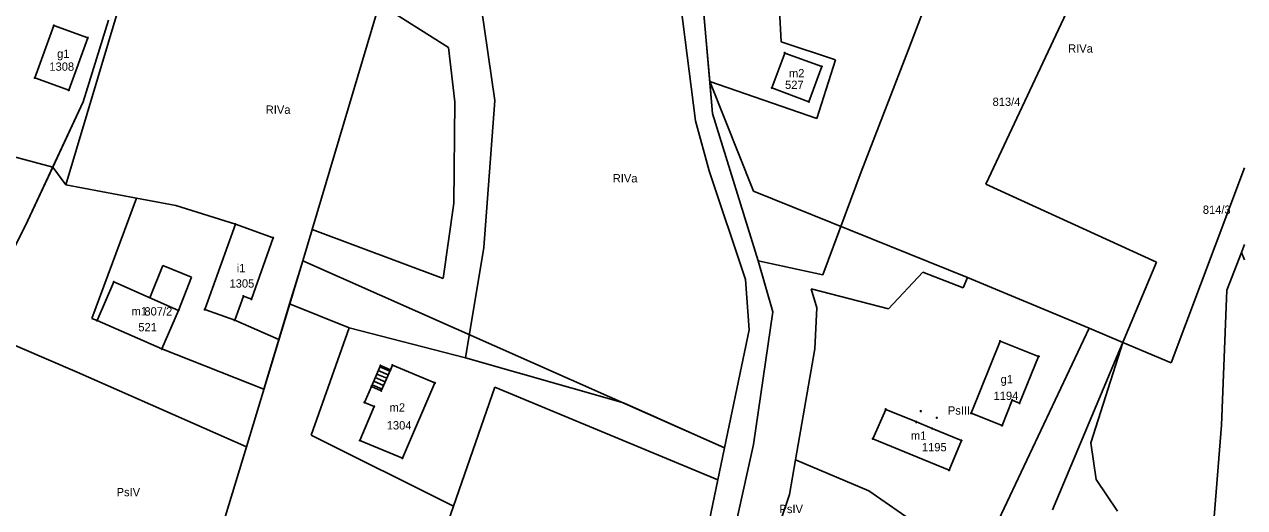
# Model space of a CAD drawing. Extents: x 7498273 to 7499989, y 5499795 to 5500810.
# Drawn here: x 7499768.9 to 7499988.9, y 5500368.1 to 5500455.2 of the extents above; entities that cross this region are included whole.
import ezdxf

# ---------------------------------------------------------------- set-up
doc = ezdxf.new("R2010")
doc.units = 0
for name, color, linetype in [('209-oznaczenie konturu klasyfikacyjnego', 7, 'Continuous'), ('211-numer działki ewidencyjnej', 7, 'Continuous'), ('217-kontur klasyfikacyjny', 7, 'Continuous'), ('218-kontur użytku gruntowego', 7, 'Continuous'), ('219-działka ewidencyjna', 7, 'Continuous'), ('312-budynek ewidencyjny', 7, 'Continuous'), ('312-oznaczenie budynku ewidencyjnego', 7, 'Continuous'), ('312-oznaczenie budynku ewidencyjnego-Atr117', 7, 'Continuous'), ('352-schody', 7, 'Continuous'), ('Punkt budynku', 7, 'Continuous')]:
    doc.layers.add(name, color=color, linetype=linetype)

# ---------------------------------------------------------------- blocks, each defined once
blk = doc.blocks.new('PUNKTBUD')
blk.add_circle((0, 0), 0.09)

msp = doc.modelspace()

# ---------------------------------------------------------------- linework, layer by layer
at = {"layer": '217-kontur klasyfikacyjny'}
for points in [[(7499791.73, 5500477.78), (7499776.34, 5500426.27)], [(7499845.38, 5500451.07), (7499807.05, 5500475.27)], [(7499889.91, 5500437.86), (7499886.1, 5500467.61)], [(7499904.64, 5500464.65), (7499905.33, 5500452.05)], [(7499851.23, 5500458.52), (7499853.72, 5500441.52)], [(7499784.04, 5500455.98), (7499779.48, 5500441.28)], [(7499905.33, 5500452.05), (7499915.14, 5500448.84)], [(7499846.48, 5500441.28), (7499845.38, 5500451.07)], [(7499915.14, 5500448.84), (7499911.74, 5500438.24)], [(7499900.36, 5500425.15), (7499892.44, 5500444.94)], [(7499892.44, 5500444.94), (7499892.94, 5500439.15)], [(7499911.74, 5500438.24), (7499892.44, 5500444.94)], [(7499779.48, 5500441.28), (7499774, 5500429.5)], [(7499846.31, 5500422.98), (7499846.48, 5500441.28)], [(7499853.72, 5500441.52), (7499851.71, 5500415.02)], [(7499892.94, 5500439.15), (7499901.18, 5500412.6)], [(7499892.35, 5500428.8), (7499889.91, 5500437.86)], [(7499774, 5500429.5), (7499764.8, 5500431.96)], [(7499769.06, 5500418.86), (7499774, 5500429.5)], [(7499774, 5500429.5), (7499776.34, 5500426.27)], [(7499975.64, 5500394.23), (7499988.876, 5500429.339)], [(7499898.91, 5500409.21), (7499892.35, 5500428.8)], [(7499776.34, 5500426.27), (7499789.08, 5500423.88)], [(7499938.93, 5500409.6), (7499900.36, 5500425.15)], [(7499781.08, 5500402.21), (7499789.08, 5500423.88)], [(7499789.08, 5500423.88), (7499796.18, 5500422.56)], [(7499796.18, 5500422.56), (7499806.94, 5500419.18)], [(7499844.37, 5500409.4), (7499846.31, 5500422.98)], [(7499762.17, 5500405.33), (7499769.06, 5500418.86)], [(7499806.94, 5500419.18), (7499813.76, 5500416.74)], [(7499819.07, 5500412.57), (7499820.76, 5500418.24)], [(7499820.76, 5500418.24), (7499844.37, 5500409.4)], [(7499813.76, 5500416.74), (7499809.81, 5500405.71)], [(7499851.71, 5500415.02), (7499848.4, 5500395.08)], [(7499985.69, 5500407.28), (7499988.34, 5500414.09)], [(7499988.34, 5500414.09), (7499988.876, 5500412.747)], [(7499816.72, 5500404.82), (7499819.07, 5500412.57)], [(7499901.18, 5500412.6), (7499903.83, 5500403.38)], [(7499924.65, 5500403.92), (7499930.86, 5500410.57)], [(7499930.86, 5500410.57), (7499938.13, 5500407.74)], [(7499938.13, 5500407.74), (7499938.93, 5500409.6)], [(7499938.93, 5500409.6), (7499960.84, 5500400.43)], [(7499899.54, 5500400.13), (7499898.91, 5500409.21)], [(7499911.74, 5500404.13), (7499910.72, 5500407.53)], [(7499910.72, 5500407.53), (7499924.65, 5500403.92)], [(7499984.72, 5500382.95), (7499985.69, 5500407.28)], [(7499808.38, 5500406.22), (7499806.82, 5500401.88)], [(7499809.81, 5500405.71), (7499808.38, 5500406.22)], [(7499814.79, 5500398.42), (7499816.72, 5500404.82)], [(7499816.72, 5500404.82), (7499827.44, 5500400.49)], [(7499903.83, 5500403.38), (7499900.37, 5500379.5)], [(7499911.39, 5500396.75), (7499911.74, 5500404.13)], [(7499782.01, 5500401.82), (7499781.08, 5500402.21)], [(7499793.7, 5500396.7), (7499782.01, 5500401.82)], [(7499806.82, 5500401.88), (7499814.79, 5500398.42)], [(7499814.79, 5500398.42), (7499812.07, 5500389.44)], [(7499820.62, 5500381.19), (7499827.44, 5500400.49)], [(7499827.44, 5500400.49), (7499848.4, 5500395.08)], [(7499895.13, 5500378.9), (7499899.54, 5500400.13)], [(7499940.42, 5500357.17), (7499960.84, 5500400.43)], [(7499960.84, 5500400.43), (7499966.92, 5500397.88)], [(7499812.07, 5500389.44), (7499793.7, 5500396.7)], [(7499907.92, 5500376.74), (7499911.39, 5500396.75)], [(7499961.13, 5500379.8), (7499966.92, 5500397.88)], [(7499966.92, 5500397.88), (7499975.64, 5500394.23)], [(7499848.4, 5500395.08), (7499876.88, 5500386.98)], [(7499853.69, 5500389.79), (7499846.27, 5500368.35)], [(7499893.92, 5500373.1), (7499853.69, 5500389.79)], [(7499876.88, 5500386.98), (7499895.13, 5500378.9)], [(7499982.91, 5500360.43), (7499984.72, 5500382.95)], [(7499846.27, 5500368.35), (7499820.62, 5500381.19)], [(7499900.37, 5500379.5), (7499891.63, 5500340.17)], [(7499962.1, 5500373.16), (7499961.13, 5500379.8)], [(7499906.84, 5500370.47), (7499907.92, 5500376.74)], [(7499921.16, 5500371.13), (7499907.92, 5500376.74)], [(7499889.66, 5500352.63), (7499893.92, 5500373.1)], [(7499965.98, 5500367.46), (7499962.1, 5500373.16)], [(7499900.55, 5500351.78), (7499906.84, 5500370.47)], [(7499935.88, 5500360.91), (7499921.16, 5500371.13)], [(7499846.27, 5500368.35), (7499839.6, 5500349.11)]]:
    msp.add_lwpolyline(points, dxfattribs=at)
at = {"layer": '218-kontur użytku gruntowego'}
for points in [[(7499791.73, 5500477.78), (7499776.34, 5500426.27)], [(7499845.38, 5500451.07), (7499807.05, 5500475.27)], [(7499890.32, 5500469.18), (7499892.44, 5500444.94)], [(7499889.91, 5500437.86), (7499886.1, 5500467.61)], [(7499904.64, 5500464.65), (7499905.33, 5500452.05)], [(7499851.23, 5500458.52), (7499853.72, 5500441.52)], [(7499784.04, 5500455.98), (7499779.48, 5500441.28)], [(7499905.33, 5500452.05), (7499915.14, 5500448.84)], [(7499846.48, 5500441.28), (7499845.38, 5500451.07)], [(7499915.14, 5500448.84), (7499911.74, 5500438.24)], [(7499900.36, 5500425.15), (7499892.44, 5500444.94)], [(7499892.44, 5500444.94), (7499892.94, 5500439.15)], [(7499911.74, 5500438.24), (7499892.44, 5500444.94)], [(7499779.48, 5500441.28), (7499774, 5500429.5)], [(7499846.31, 5500422.98), (7499846.48, 5500441.28)], [(7499853.72, 5500441.52), (7499851.71, 5500415.02)], [(7499892.94, 5500439.15), (7499901.18, 5500412.6)], [(7499892.35, 5500428.8), (7499889.91, 5500437.86)], [(7499774, 5500429.5), (7499764.8, 5500431.96)], [(7499769.06, 5500418.86), (7499774, 5500429.5)], [(7499774, 5500429.5), (7499776.34, 5500426.27)], [(7499975.64, 5500394.23), (7499988.876, 5500429.339)], [(7499898.91, 5500409.21), (7499892.35, 5500428.8)], [(7499776.34, 5500426.27), (7499789.08, 5500423.88)], [(7499938.93, 5500409.6), (7499900.36, 5500425.15)], [(7499789.08, 5500423.88), (7499781.08, 5500402.21)], [(7499789.08, 5500423.88), (7499796.18, 5500422.56)], [(7499796.18, 5500422.56), (7499806.94, 5500419.18)], [(7499844.37, 5500409.4), (7499846.31, 5500422.98)], [(7499762.17, 5500405.33), (7499769.06, 5500418.86)], [(7499806.94, 5500419.18), (7499813.76, 5500416.74)], [(7499819.07, 5500412.57), (7499820.76, 5500418.24)], [(7499820.76, 5500418.24), (7499844.37, 5500409.4)], [(7499813.76, 5500416.74), (7499809.81, 5500405.71)], [(7499851.71, 5500415.02), (7499848.4, 5500395.08)], [(7499985.69, 5500407.28), (7499988.34, 5500414.09)], [(7499988.34, 5500414.09), (7499988.876, 5500412.747)], [(7499816.72, 5500404.82), (7499819.07, 5500412.57)], [(7499901.18, 5500412.6), (7499903.83, 5500403.38)], [(7499924.65, 5500403.92), (7499930.86, 5500410.57)], [(7499930.86, 5500410.57), (7499938.13, 5500407.74)], [(7499938.13, 5500407.74), (7499938.93, 5500409.6)], [(7499938.93, 5500409.6), (7499960.84, 5500400.43)], [(7499899.54, 5500400.13), (7499898.91, 5500409.21)], [(7499911.74, 5500404.13), (7499910.72, 5500407.53)], [(7499910.72, 5500407.53), (7499924.65, 5500403.92)], [(7499984.72, 5500382.95), (7499985.69, 5500407.28)], [(7499808.38, 5500406.22), (7499806.82, 5500401.88)], [(7499809.81, 5500405.71), (7499808.38, 5500406.22)], [(7499814.79, 5500398.42), (7499816.72, 5500404.82)], [(7499816.72, 5500404.82), (7499827.44, 5500400.49)], [(7499903.83, 5500403.38), (7499900.37, 5500379.5)], [(7499911.39, 5500396.75), (7499911.74, 5500404.13)], [(7499781.08, 5500402.21), (7499782.01, 5500401.82)], [(7499782.01, 5500401.82), (7499793.7, 5500396.7)], [(7499806.82, 5500401.88), (7499814.79, 5500398.42)], [(7499812.07, 5500389.44), (7499814.79, 5500398.42)], [(7499827.44, 5500400.49), (7499820.62, 5500381.19)], [(7499848.4, 5500395.08), (7499827.44, 5500400.49)], [(7499895.13, 5500378.9), (7499899.54, 5500400.13)], [(7499940.42, 5500357.17), (7499960.84, 5500400.43)], [(7499960.84, 5500400.43), (7499966.92, 5500397.88)], [(7499793.7, 5500396.7), (7499812.07, 5500389.44)], [(7499907.92, 5500376.74), (7499911.39, 5500396.75)], [(7499961.13, 5500379.8), (7499966.92, 5500397.88)], [(7499966.92, 5500397.88), (7499975.64, 5500394.23)], [(7499876.88, 5500386.98), (7499848.4, 5500395.08)], [(7499846.27, 5500368.35), (7499853.69, 5500389.79)], [(7499853.69, 5500389.79), (7499893.92, 5500373.1)], [(7499895.13, 5500378.9), (7499876.88, 5500386.98)], [(7499982.91, 5500360.43), (7499984.72, 5500382.95)], [(7499820.62, 5500381.19), (7499846.27, 5500368.35)], [(7499900.37, 5500379.5), (7499891.63, 5500340.17)], [(7499893.92, 5500373.1), (7499895.13, 5500378.9)], [(7499962.1, 5500373.16), (7499961.13, 5500379.8)], [(7499906.84, 5500370.47), (7499907.92, 5500376.74)], [(7499921.16, 5500371.13), (7499907.92, 5500376.74)], [(7499889.66, 5500352.63), (7499893.92, 5500373.1)], [(7499965.98, 5500367.46), (7499962.1, 5500373.16)], [(7499900.55, 5500351.78), (7499906.84, 5500370.47)], [(7499935.88, 5500360.91), (7499921.16, 5500371.13)], [(7499846.27, 5500368.35), (7499839.6, 5500349.11)]]:
    msp.add_lwpolyline(points, dxfattribs=at)
at = {"layer": '219-działka ewidencyjna'}
for points in [[(7499828.16, 5500443.04), (7499845.34, 5500500.79)], [(7499942.21, 5500426.39), (7499977.31, 5500501.15)], [(7499928.28, 5500450.71), (7499939.56, 5500480.36)], [(7499889.56, 5500477.93), (7499892.94, 5500439.15)], [(7499886.1, 5500467.61), (7499889.91, 5500437.86)], [(7499784.04, 5500455.98), (7499779.48, 5500441.28)], [(7499919.75, 5500428.66), (7499928.28, 5500450.71)], [(7499819.07, 5500412.57), (7499828.16, 5500443.04)], [(7499769.06, 5500418.86), (7499779.48, 5500441.28)], [(7499892.94, 5500439.15), (7499901.18, 5500412.6)], [(7499889.91, 5500437.86), (7499892.35, 5500428.8)], [(7499892.35, 5500428.8), (7499898.91, 5500409.21)], [(7499912.83, 5500410.05), (7499919.75, 5500428.66)], [(7499942.21, 5500426.39), (7499973, 5500412.34)], [(7499762.17, 5500405.33), (7499769.06, 5500418.86)], [(7499985.69, 5500407.28), (7499988.34, 5500414.09)], [(7499988.34, 5500414.09), (7499988.876, 5500415.534)], [(7499988.34, 5500414.09), (7499988.876, 5500412.744)], [(7499791.49, 5500405.92), (7499793.86, 5500411.75)], [(7499793.86, 5500411.75), (7499799.05, 5500409.67)], [(7499808.92, 5500379.03), (7499819.07, 5500412.57)], [(7499819.07, 5500412.57), (7499895.13, 5500378.9)], [(7499903.83, 5500403.38), (7499901.18, 5500412.6)], [(7499901.18, 5500412.6), (7499912.83, 5500410.05)], [(7499954.25, 5500367.72), (7499973, 5500412.34)], [(7499796.67, 5500403.63), (7499799.05, 5500409.67)], [(7499782.01, 5500401.82), (7499785.01, 5500408.79)], [(7499785.01, 5500408.79), (7499791.49, 5500405.92)], [(7499898.91, 5500409.21), (7499899.54, 5500400.13)], [(7499984.72, 5500382.95), (7499985.69, 5500407.28)], [(7499793.7, 5500396.7), (7499796.67, 5500403.63)], [(7499900.37, 5500379.5), (7499903.83, 5500403.38)], [(7499758.11, 5500401.23), (7499778.39, 5500392.51)], [(7499782.01, 5500401.82), (7499793.7, 5500396.7)], [(7499895.13, 5500378.9), (7499899.54, 5500400.13)], [(7499778.39, 5500392.51), (7499808.92, 5500379.03)], [(7499982.91, 5500360.43), (7499984.72, 5500382.95)], [(7499797.92, 5500342.97), (7499808.92, 5500379.03)], [(7499889.66, 5500352.63), (7499895.13, 5500378.9)], [(7499900.37, 5500379.5), (7499891.63, 5500340.17)]]:
    msp.add_lwpolyline(points, dxfattribs=at)
at = {"layer": '312-budynek ewidencyjny'}
for points in [[(7499770.77, 5500445.57), (7499774.22, 5500455.04)], [(7499774.22, 5500455.04), (7499780.34, 5500452.82)], [(7499780.34, 5500452.82), (7499776.89, 5500443.34)], [(7499903.66, 5500443.77), (7499905.98, 5500450.06)], [(7499905.98, 5500450.06), (7499912.64, 5500447.63)], [(7499912.64, 5500447.63), (7499910.32, 5500441.28)], [(7499776.89, 5500443.34), (7499770.77, 5500445.57)], [(7499910.32, 5500441.28), (7499903.66, 5500443.77)], [(7499801.43, 5500403.82), (7499806.94, 5500419.18)], [(7499806.94, 5500419.18), (7499813.76, 5500416.74)], [(7499813.76, 5500416.74), (7499809.81, 5500405.71)], [(7499782.01, 5500401.82), (7499785.01, 5500408.79)], [(7499785.01, 5500408.79), (7499796.67, 5500403.63)], [(7499808.38, 5500406.22), (7499806.82, 5500401.88)], [(7499809.81, 5500405.71), (7499808.38, 5500406.22)], [(7499796.67, 5500403.63), (7499793.7, 5500396.7)], [(7499806.82, 5500401.88), (7499801.43, 5500403.82)], [(7499793.7, 5500396.7), (7499782.01, 5500401.82)], [(7499939.56, 5500385.11), (7499944.81, 5500398.11)], [(7499944.81, 5500398.11), (7499951.75, 5500395.37)], [(7499951.75, 5500395.37), (7499948.32, 5500386.93)], [(7499833.24, 5500389.17), (7499834.87, 5500392.93)], [(7499834.87, 5500392.93), (7499835.25, 5500393.8)], [(7499835.25, 5500393.8), (7499842.89, 5500390.57)], [(7499830.2, 5500387.06), (7499831.45, 5500389.94)], [(7499831.45, 5500389.94), (7499833.24, 5500389.17)], [(7499842.89, 5500390.57), (7499837.04, 5500377.02)], [(7499946.98, 5500387.49), (7499945.16, 5500382.89)], [(7499948.32, 5500386.93), (7499946.98, 5500387.49)], [(7499829.4, 5500380.22), (7499831.96, 5500386.33)], [(7499831.96, 5500386.33), (7499830.2, 5500387.06)], [(7499921.85, 5500380.51), (7499924.19, 5500385.82)], [(7499924.19, 5500385.82), (7499929.7, 5500383.54)], [(7499929.7, 5500383.54), (7499932.57, 5500382.36)], [(7499945.16, 5500382.89), (7499939.56, 5500385.11)], [(7499932.57, 5500382.36), (7499937.82, 5500380.19)], [(7499837.04, 5500377.02), (7499829.4, 5500380.22)], [(7499935.61, 5500374.83), (7499921.85, 5500380.51)], [(7499937.82, 5500380.19), (7499935.61, 5500374.83)]]:
    msp.add_lwpolyline(points, dxfattribs=at)
at = {"layer": '352-schody'}
msp.add_lwpolyline([(7499831.45, 5500389.94), (7499833.08, 5500393.7), (7499834.87, 5500392.93), (7499833.24, 5500389.17)], close=True, dxfattribs=at)
msp.add_lwpolyline([(7499831.45, 5500389.94), (7499833.08, 5500393.7), (7499834.87, 5500392.93), (7499833.24, 5500389.17)], close=True, dxfattribs=at)
for points in [[(7499834.212, 5500391.413), (7499832.424, 5500392.188)], [(7499834.491, 5500392.055), (7499832.703, 5500392.83)], [(7499834.769, 5500392.697), (7499832.981, 5500393.472)], [(7499833.377, 5500389.486), (7499831.589, 5500390.261)], [(7499833.655, 5500390.128), (7499831.868, 5500390.903)], [(7499833.934, 5500390.771), (7499832.146, 5500391.546)]]:
    msp.add_lwpolyline(points, dxfattribs=at)

# ---------------------------------------------------------------- block references
at = {"layer": 'Punkt budynku'}
for p in [(7499774.22, 5500455.04), (7499780.34, 5500452.82), (7499905.98, 5500450.06), (7499912.64, 5500447.63), (7499770.77, 5500445.57), (7499776.89, 5500443.34), (7499903.66, 5500443.77), (7499910.32, 5500441.28), (7499806.94, 5500419.18), (7499813.76, 5500416.74), (7499785.01, 5500408.79), (7499808.38, 5500406.22), (7499809.81, 5500405.71), (7499796.67, 5500403.63), (7499801.43, 5500403.82), (7499782.01, 5500401.82), (7499806.82, 5500401.88), (7499793.7, 5500396.7), (7499944.81, 5500398.11), (7499951.75, 5500395.37), (7499833.08, 5500393.7), (7499834.87, 5500392.93), (7499835.25, 5500393.8), (7499831.45, 5500389.94), (7499842.89, 5500390.57), (7499833.24, 5500389.17), (7499946.98, 5500387.49), (7499830.2, 5500387.06), (7499831.96, 5500386.33), (7499924.19, 5500385.82), (7499930.51, 5500385.49), (7499939.56, 5500385.11), (7499948.32, 5500386.93), (7499929.7, 5500383.54), (7499933.38, 5500384.31), (7499945.16, 5500382.89), (7499932.57, 5500382.36), (7499829.4, 5500380.22), (7499921.85, 5500380.51), (7499937.82, 5500380.19), (7499837.04, 5500377.02), (7499935.61, 5500374.83)]:
    msp.add_blockref('PUNKTBUD', p, dxfattribs=at)

# ---------------------------------------------------------------- texts
at = {"layer": '209-oznaczenie konturu klasyfikacyjnego'}
for s, p in [('RIVa', (7499957.06, 5500450.13)), ('RIVa', (7499812.41, 5500439.1)), ('RIVa', (7499874.97, 5500426.73)), ('PsIII', (7499935.38, 5500384.87)), ('PsIV', (7499785.52, 5500370.15)), ('PsIV', (7499905.02, 5500367.11))]:
    msp.add_text(s, height=1.5, dxfattribs=at).set_placement(p)
at = {"layer": '211-numer działki ewidencyjnej'}
for s, p in [('813/4', (7499943.44, 5500440.52)), ('814/3', (7499981.35, 5500421.06)), ('807/2', (7499790.53, 5500402.73))]:
    msp.add_text(s, height=1.5, dxfattribs=at).set_placement(p)
at = {"layer": '312-oznaczenie budynku ewidencyjnego'}
for s, p in [('1308', (7499773.4, 5500446.86)), ('527', (7499906.03, 5500443.58)), ('1305', (7499805.88, 5500407.76)), ('521', (7499789.44, 5500399.88)), ('1194', (7499943.62, 5500387.51)), ('1304', (7499834.22, 5500382.19)), ('1195', (7499930.7, 5500378.25))]:
    msp.add_text(s, height=1.5, dxfattribs=at).set_placement(p)
at = {"layer": '312-oznaczenie budynku ewidencyjnego-Atr117'}
for s, p in [('g1', (7499774.789, 5500449.19)), ('m2', (7499906.736, 5500445.67)), ('i1', (7499807.182, 5500410.53)), ('m1', (7499788.215, 5500402.75)), ('g1', (7499944.889, 5500390.5)), ('m2', (7499834.736, 5500385.41)), ('m1', (7499928.715, 5500380.33))]:
    msp.add_text(s, height=1.5, dxfattribs=at).set_placement(p)

doc.saveas('drawing.dxf')
